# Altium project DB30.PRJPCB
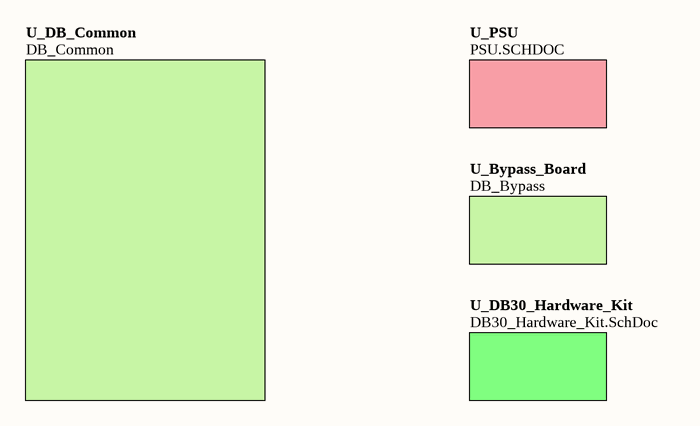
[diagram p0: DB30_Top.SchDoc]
ProjectAddress1: L3, 12A Rodborough Road; ProjectAddress2: Frenchs Forest; ProjectAddress3: NSW 2086; ProjectAddress4: Australia; ProjectAssyNum: D-820-0004; ProjectOrganization: Altium Limited; ProjectRevision: 07; ProjectTitle: DB30 - Daughter Board Spartan3; ProjectTotalSheets: 22
9 sheets, 135 parts. Net scope: hierarchical (ports join the sheet entries above them; power ports are global).
Board files: DB30_Panel.PcbDoc, DB30.PcbDoc
Sheets:
  DB30_Top.SchDoc
    U_PSU = PSU.SCHDOC
    U_DB30_Hardware_Kit = DB30_Hardware_Kit.SchDoc
  DEVICES.SchDoc
    U_FPGA = FPGA.SCHDOC
      U_FPGA_Power = FPGA_NonIO.SchDoc
      U_Bypass_3V3 = Bypass_FPGA_3V3.SchDoc
      U_Bypass_2V5 = Bypass_FPGA_2V5.SchDoc
      U_Bypass_1V2 = Bypass_FPGA_1V2.SchDoc

## Sheet DB30_Top.SchDoc: DB30 Top Level
size A4; Address1: Level 3, 12a Rodborough Rd; Address2: Frenchs Forest 2086; Address3: NSW; Address4: AUSTRALIA; SheetNumber: 2; SheetTotal: 23

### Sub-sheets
U_Bypass_Board = DB_Bypass (file not in this document): no entries
U_DB30_Hardware_Kit = DB30_Hardware_Kit.SchDoc: no entries
U_DB_Common = DB_Common (file not in this document): no entries
U_PSU = PSU.SCHDOC: no entries

## Sheet PSU.SCHDOC: Power Supply Top Level
size A4; Address1: Level 3, 12a Rodborough Rd; Address2: Frenchs Forest 2086; Address3: NSW; Address4: AUSTRALIA; SheetNumber: 10; SheetTotal: 23
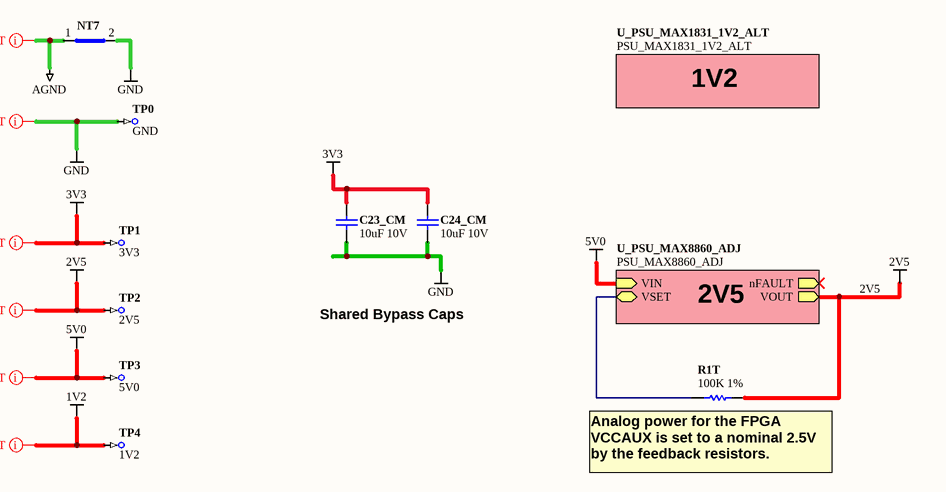
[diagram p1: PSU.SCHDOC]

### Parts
C23_CM  10uF 10V  [CAPC2012-STAR]
C24_CM  10uF 10V  [CAPC2012-STAR]
NT7  Net Tie SMT2  [NETTIE-SMT2-8X8]  (value not drawn)  (net tie, no BOM)
R1T  100K 1%  [RESC1005-STAR]
TP0  GND  [TestPin]  (no BOM)
TP1  3V3  [TestPin]  (no BOM)
TP2  2V5  [TestPin]  (no BOM)
TP3  5V0  [TestPin]  (no BOM)
TP4  1V2  [TestPin]  (no BOM)

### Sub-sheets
U_PSU_MAX1831_1V2_ALT = PSU_MAX1831_1V2_ALT (file not in this document): no entries
U_PSU_MAX8860_ADJ = PSU_MAX8860_ADJ (file not in this document): nFAULT (out), VIN (in), VOUT (out), VSET (bidir)

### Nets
1V2: TP4.1
2V5: R1T.2 TP2.1 ; sheet U_PSU_MAX8860_ADJ/VOUT
3V3: C23_CM.1 C24_CM.1 TP1.1
5V0: TP3.1 ; sheet U_PSU_MAX8860_ADJ/VIN
AGND: NT7.1(Net1)
GND: C23_CM.2 C24_CM.2 NT7.2(Net2) TP0.1
NetR1T_1: R1T.1 ; sheet U_PSU_MAX8860_ADJ/VSET

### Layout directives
net class PWRNET: 1V2, 2V5, 3V3, 5V0, AGND, GND

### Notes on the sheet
- 1V2
- Shared Bypass Caps
- 2V5
- (near R1T) Analog power for the FPGA VCCAUX is set to a nominal 2.5V by the feedback resistors.

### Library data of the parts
C23_CM C24_CM = D-101-0087: Capacitor, Ceramic, 10uF 10% 10V 0805 (2012) X5R; Polarity: Non-Polarized
NT7 = D-002-0002: Net-Tie, Surface Mount, 2 x 0.4mm x 0.2mm SMT Pads - For 0.2mm Track
R1T = D-100-0132: Resistor, 100K 1% 0402 (1005); Power Rating: 63 mW
TP0-TP4 = D-006-0000: Test Point, PCB Mount with Silkscreen Box

## Sheet DB30_Hardware_Kit.SchDoc: DB30 Hardware Kit
size A4; Address1: Level 3, 12a Rodborough Rd; Address2: Frenchs Forest 2086; Address3: NSW; Address4: AUSTRALIA; SheetNumber: 9; SheetTotal: 23
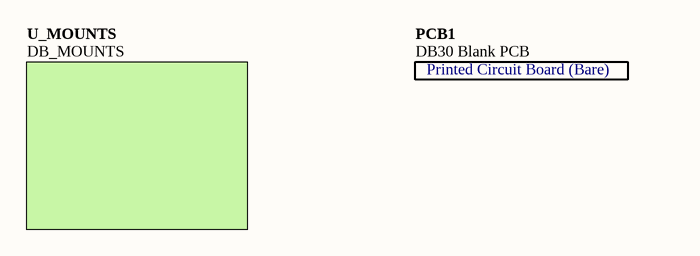
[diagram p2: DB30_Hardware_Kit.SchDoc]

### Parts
PCB1  DB30 Blank PCB  (mechanical)

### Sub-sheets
U_MOUNTS = DB_MOUNTS (file not in this document): no entries

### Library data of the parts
PCB1 = D-810-0004: DB30 Blank PCB - Daughter Board Xilinx Spartan3 XC3S1500-4FG676C; ProjectPath: DB30.PrjPCB

## Sheet DEVICES.SchDoc: FPGA, LEDs and SRAM Memory
size A4; Address1: Level 3, 12a Rodborough Rd; Address2: Frenchs Forest 2086; Address3: NSW; Address4: AUSTRALIA; SheetNumber: 3; SheetTotal: 23
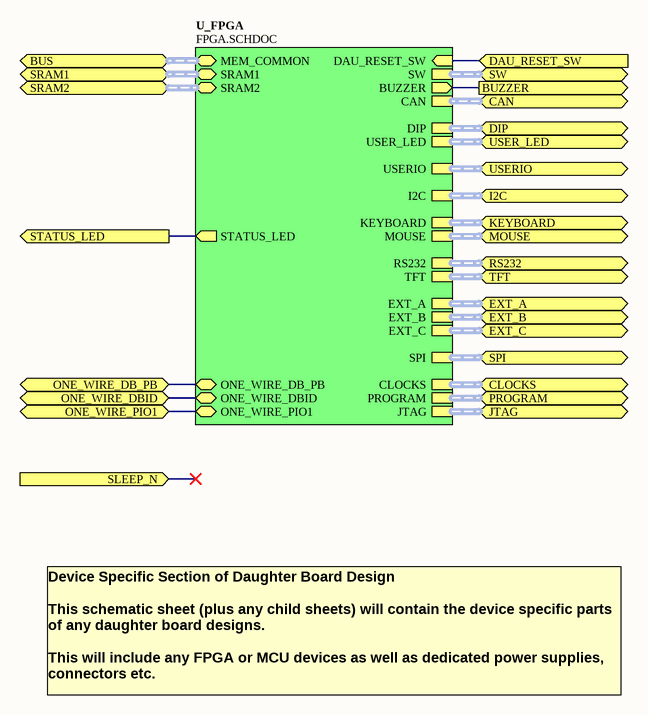
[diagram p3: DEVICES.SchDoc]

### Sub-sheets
U_FPGA = FPGA.SCHDOC: SRAM1 (harness SRAM-256Kx16), SRAM2 (harness SRAM-256Kx16), MEM_COMMON (harness HOSTMEMORY), DAU_RESET_SW (in), BUZZER (out), ONE_WIRE_DBID (bidir), ONE_WIRE_DB_PB (bidir), ONE_WIRE_PIO1 (bidir), JTAG (harness HardSoft_JTAG), SW (harness SW5), DIP (harness SW8), USERIO (harness IO36), EXT_A (harness PBIO), EXT_B (harness PBIO), EXT_C (harness PBIO), USER_LED (harness LED8), SPI (harness DAU_SPI), I2C (harness I2C), CAN (harness CAN_INT), RS232 (harness RS232_INT), KEYBOARD (harness PS2), MOUSE (harness PS2), TFT (harness DAU_TFT), PROGRAM (harness DAU_CTRL), CLOCKS (harness DAU_CLK), STATUS_LED (out)

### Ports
BUS (harness HOSTMEMORY), BUZZER (out), CAN, CLOCKS, DAU_RESET_SW (in), DIP, EXT_A, EXT_B, EXT_C, I2C, JTAG, KEYBOARD, MOUSE, ONE_WIRE_DB_PB (bidir), ONE_WIRE_DBID (bidir), ONE_WIRE_PIO1 (bidir), PROGRAM, RS232, SLEEP_N (in), SPI, SRAM1, SRAM2 (harness SRAM-256Kx16), STATUS_LED (out), SW, TFT, USER_LED, USERIO

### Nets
BUZZER: port BUZZER, sheet U_FPGA/BUZZER
DAU_RESET_SW: port DAU_RESET_SW, sheet U_FPGA/DAU_RESET_SW
ONE_WIRE_DB_PB: port ONE_WIRE_DB_PB, sheet U_FPGA/ONE_WIRE_DB_PB
ONE_WIRE_DBID: port ONE_WIRE_DBID, sheet U_FPGA/ONE_WIRE_DBID
ONE_WIRE_PIO1: port ONE_WIRE_PIO1, sheet U_FPGA/ONE_WIRE_PIO1
STATUS_LED: port STATUS_LED, sheet U_FPGA/STATUS_LED

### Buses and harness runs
harness port BUS = sheet U_FPGA/MEM_COMMON
harness port CAN = sheet U_FPGA/CAN
harness port CLOCKS = sheet U_FPGA/CLOCKS
harness port DIP = sheet U_FPGA/DIP
harness port EXT_A = sheet U_FPGA/EXT_A
harness port EXT_B = sheet U_FPGA/EXT_B
harness port EXT_C = sheet U_FPGA/EXT_C
harness port I2C = sheet U_FPGA/I2C
harness port JTAG = sheet U_FPGA/JTAG
harness port KEYBOARD = sheet U_FPGA/KEYBOARD
harness port MOUSE = sheet U_FPGA/MOUSE
harness port PROGRAM = sheet U_FPGA/PROGRAM
harness port RS232 = sheet U_FPGA/RS232
harness port SPI = sheet U_FPGA/SPI
harness port SRAM1 = sheet U_FPGA/SRAM1
harness port SRAM2 = sheet U_FPGA/SRAM2
harness port SW = sheet U_FPGA/SW
harness port TFT = sheet U_FPGA/TFT
harness port USER_LED = sheet U_FPGA/USER_LED
harness port USERIO = sheet U_FPGA/USERIO

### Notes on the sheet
- Device Specific Section of Daughter Board Design
  This schematic sheet (plus any child sheets) will contain the device specific parts of any daughter board designs.
  This will include any FPGA or MCU devices as well as dedicated power supplies, connectors etc.

## Sheet FPGA.SCHDOC: FPGA Connections
size A2; Address1: Level 3, 12a Rodborough Rd; Address2: Frenchs Forest 2086; Address3: NSW; Address4: AUSTRALIA; SheetNumber: 4; SheetTotal: 23; PageSetup: Record=PageOptions|CenterHorizontal=True|CenterVertical=True|PrintScale=0.71|XCorrection=1.00|YCorrection=1.00|PrintKind=0|BorderSize=5000000|LeftOffset=0|BottomOffset=0|Orientation=2|PaperLength=4199|PaperWidth=2969|Scale=100|PaperSource=7|PrintQuality=600|MediaType=1|DitherType=10|PaperKind=A3 (297 x 420 mm)|PrintScaleMode=1
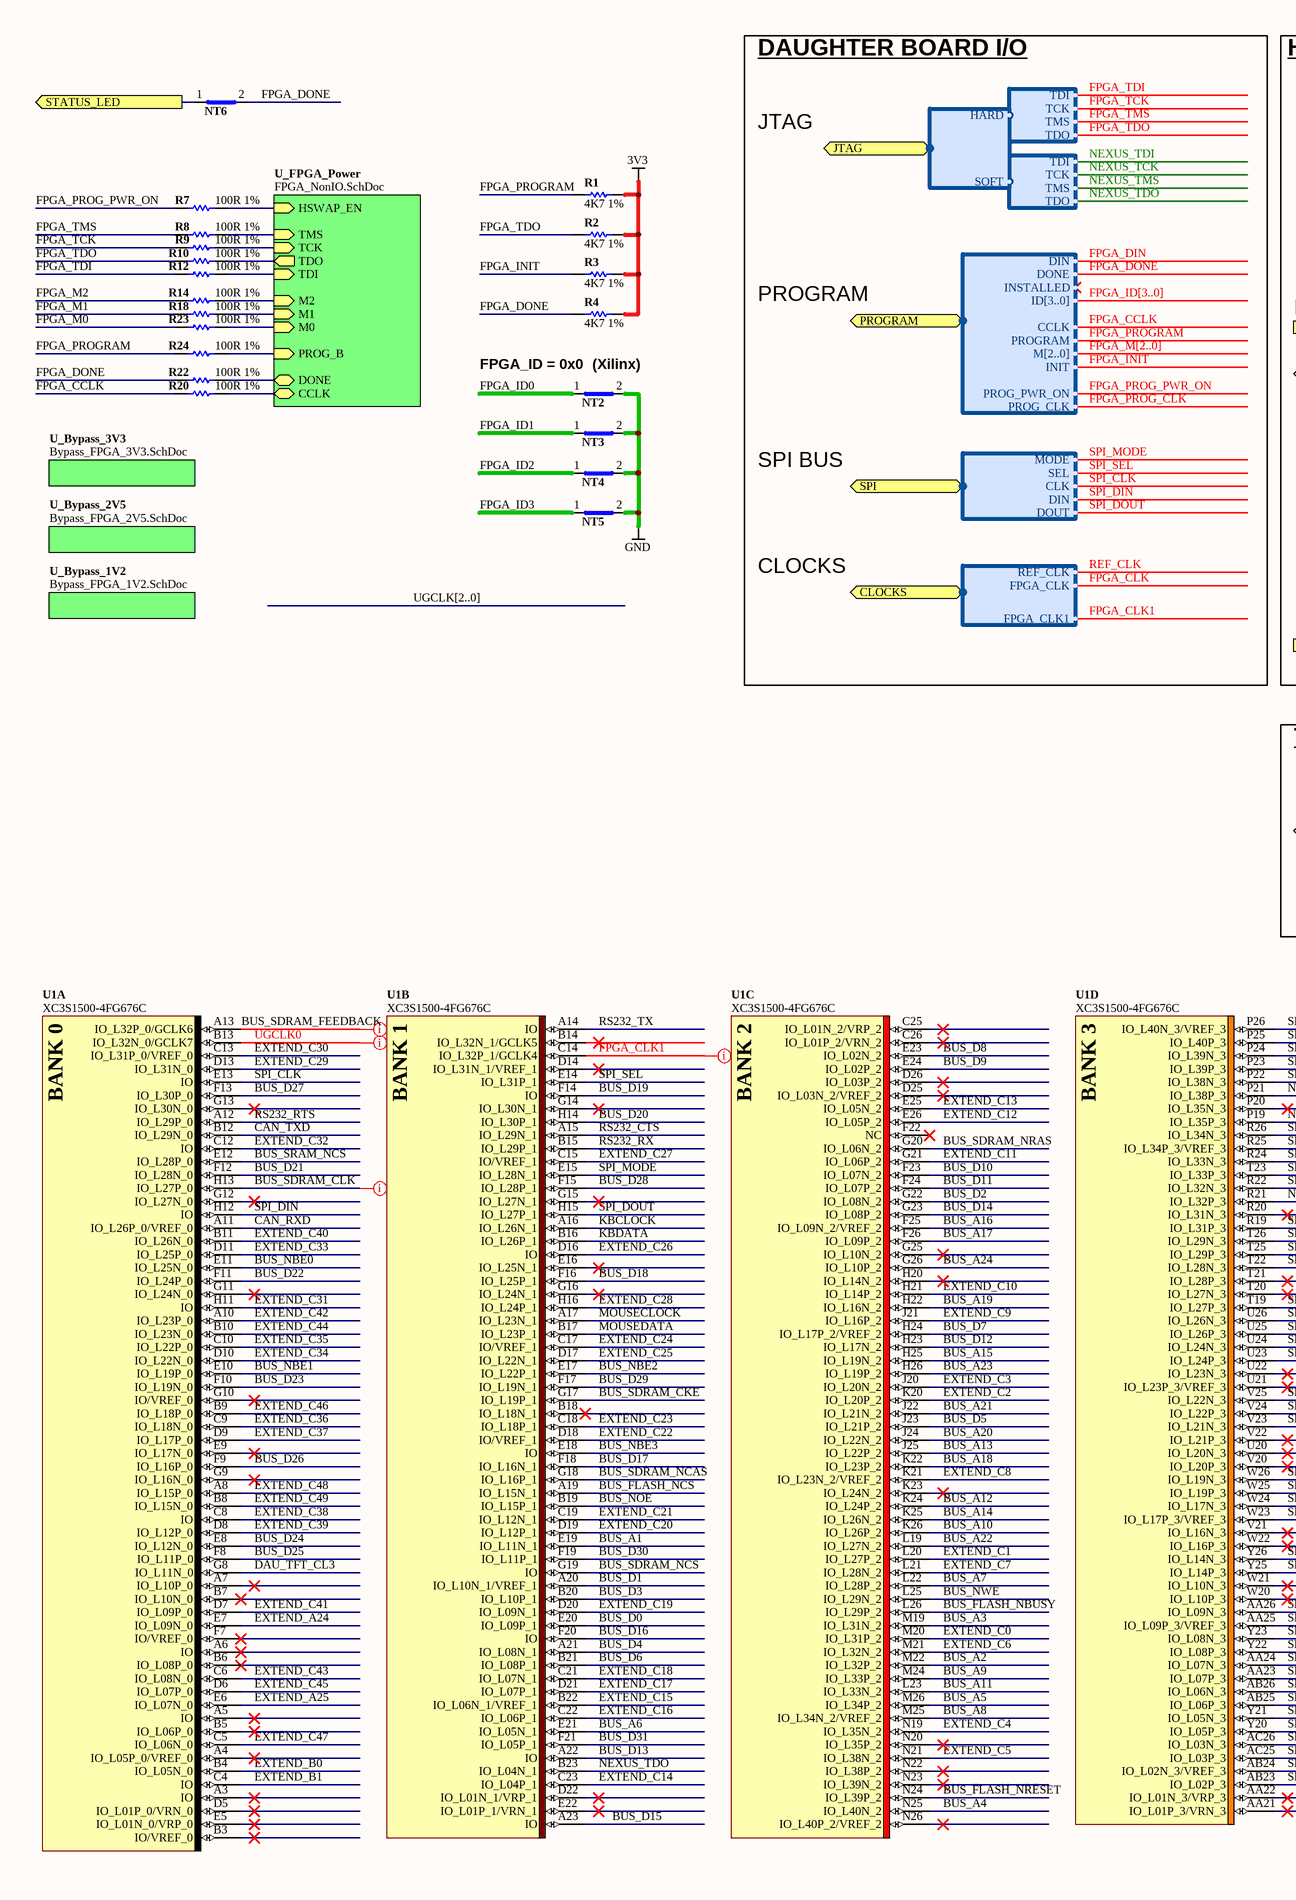
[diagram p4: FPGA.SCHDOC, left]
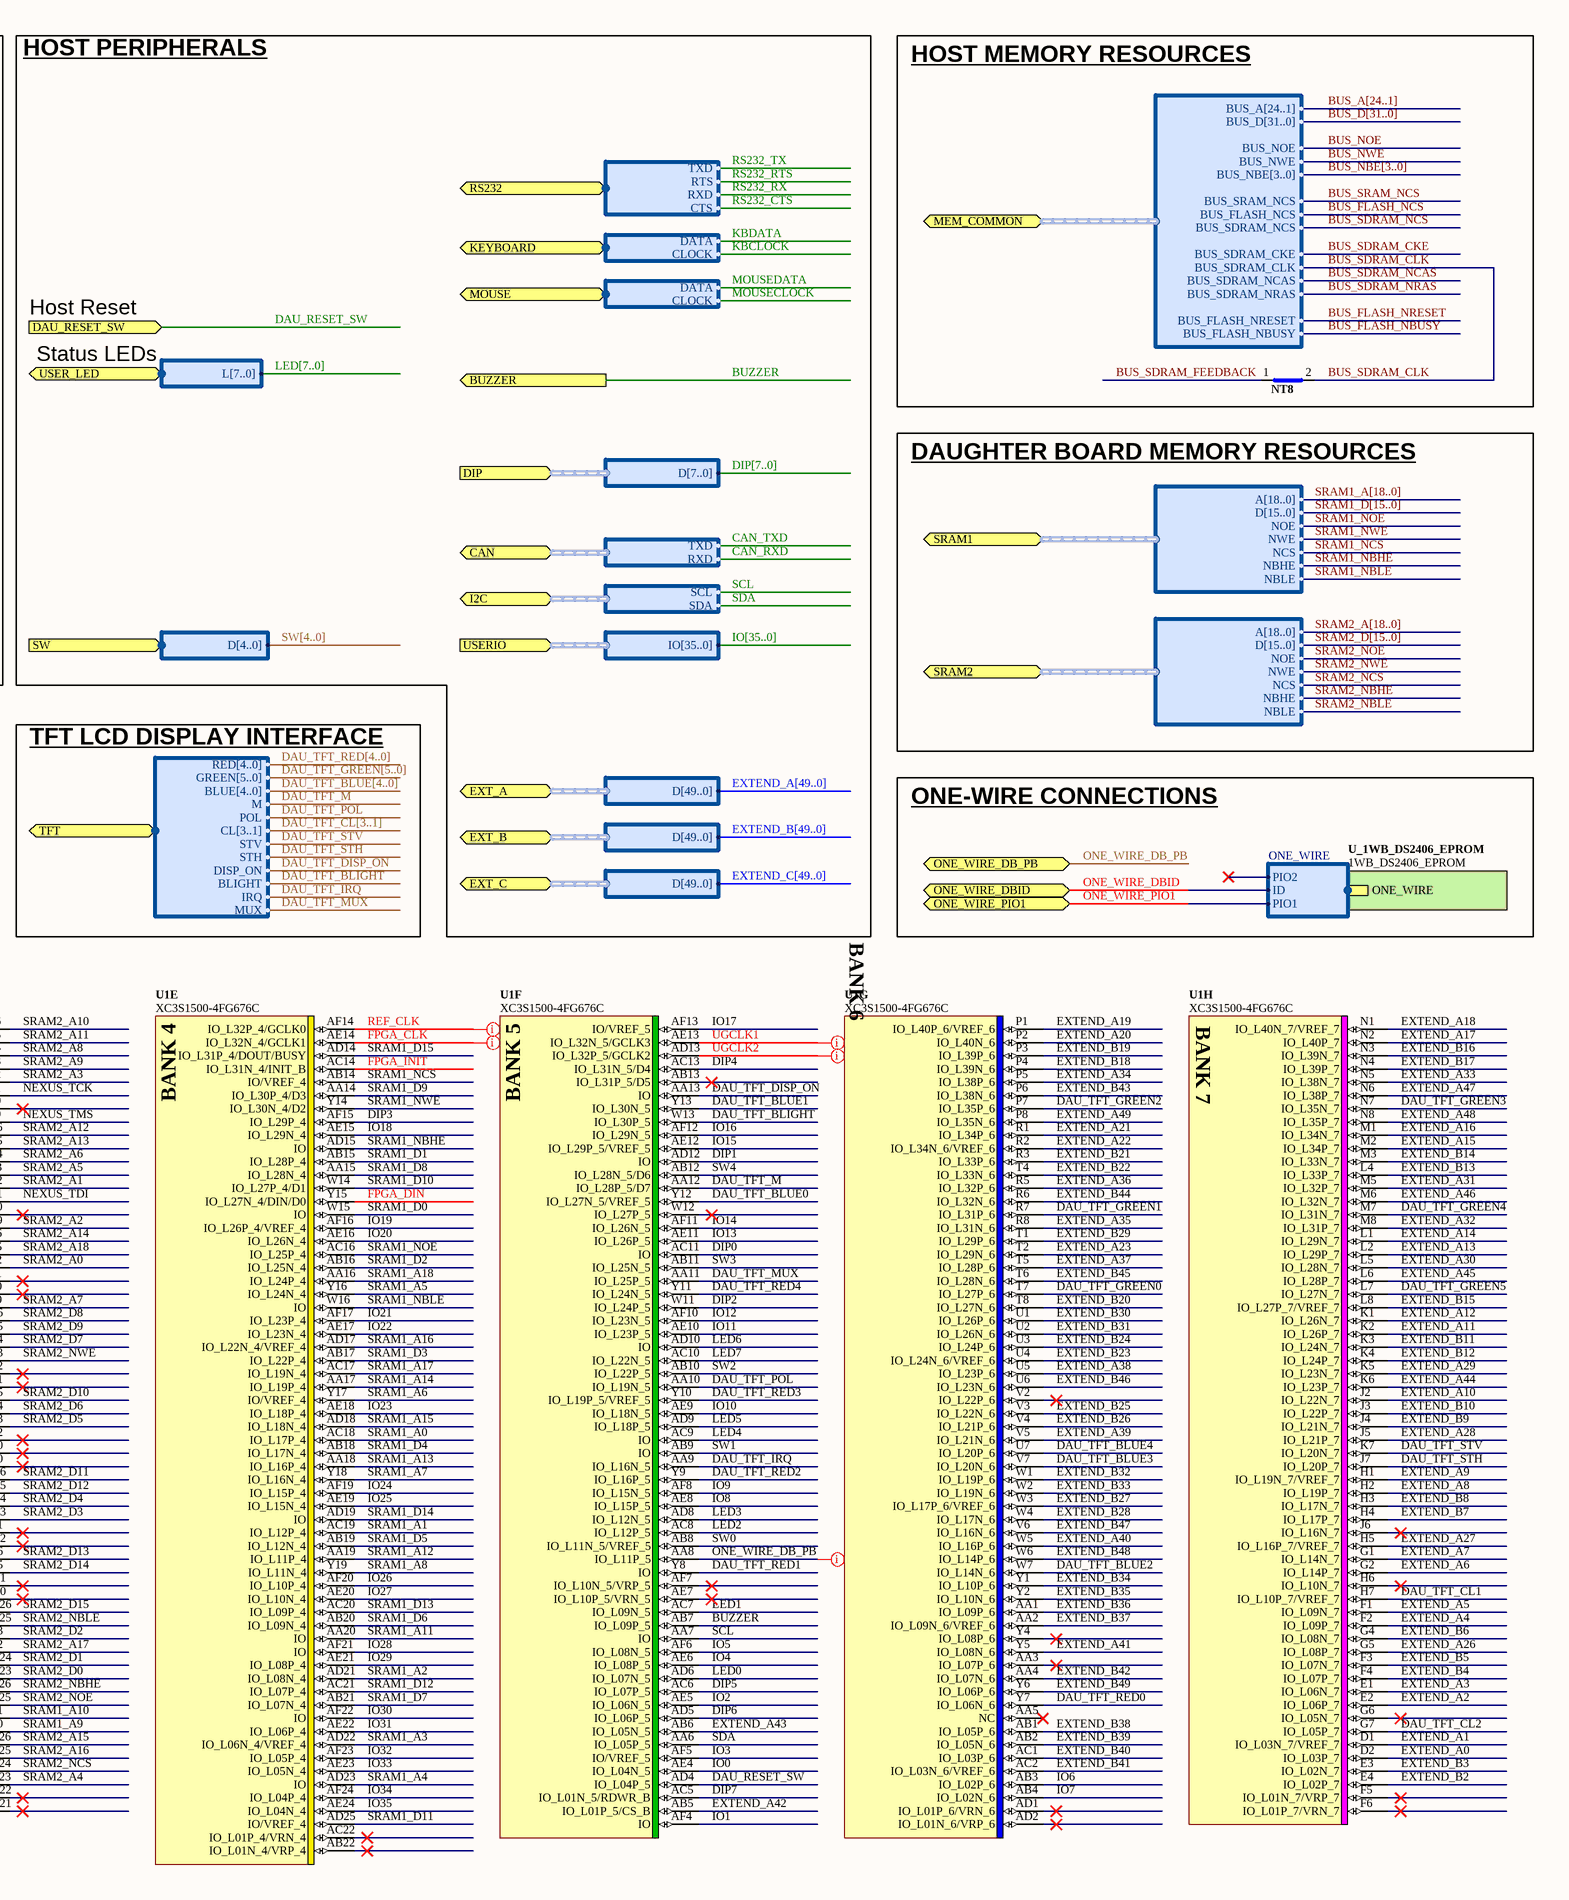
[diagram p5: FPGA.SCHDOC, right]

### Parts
NT2  Net Tie SMT2  [NETTIE-SMT2-8X8]  (value not drawn)  (net tie, no BOM)
NT3  Net Tie SMT2  [NETTIE-SMT2-8X8]  (value not drawn)  (net tie, no BOM)
NT4  Net Tie SMT2  [NETTIE-SMT2-8X8]  (value not drawn)  (net tie, no BOM)
NT5  Net Tie SMT2  [NETTIE-SMT2-8X8]  (value not drawn)  (net tie, no BOM)
NT6  Net Tie SMT2  [NETTIE-SMT2-8X8]  (value not drawn)  (net tie, no BOM)
NT8  Net Tie SMT2  [NETTIE-SMT2-8X8]  (value not drawn)  (net tie, no BOM)
R1  4K7 1%  [RESC1005-STAR]
R2  4K7 1%  [RESC1005-STAR]
R3  4K7 1%  [RESC1005-STAR]
R4  4K7 1%  [RESC1005-STAR]
R7  100R 1%  [RESC1005-STAR]
R8  100R 1%  [RESC1005-STAR]
R9  100R 1%  [RESC1005-STAR]
R10  100R 1%  [RESC1005-STAR]
R12  100R 1%  [RESC1005-STAR]
R14  100R 1%  [RESC1005-STAR]
R18  100R 1%  [RESC1005-STAR]
R20  100R 1%  [RESC1005-STAR]
R22  100R 1%  [RESC1005-STAR]
R23  100R 1%  [RESC1005-STAR]
R24  100R 1%  [RESC1005-STAR]
U1  XC3S1500-4FG676C  [BGA100P26X26-676]  (parts A,B,C,D,E,F,G,H of 12)

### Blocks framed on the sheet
HOST MEMORY RESOURCES: NT8

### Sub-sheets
U_1WB_DS2406_EPROM = 1WB_DS2406_EPROM (file not in this document): ONE_WIRE (harness ONE_WIRE)
U_Bypass_1V2 = Bypass_FPGA_1V2.SchDoc: no entries
U_Bypass_2V5 = Bypass_FPGA_2V5.SchDoc: no entries
U_Bypass_3V3 = Bypass_FPGA_3V3.SchDoc: no entries
U_FPGA_Power = FPGA_NonIO.SchDoc: TMS (in), DONE (bidir), M1 (in), CCLK (bidir), M0 (in), M2 (in), TCK (in), HSWAP_EN (in), TDI (in), PROG_B (in), TDO (out)

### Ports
BUZZER (out), CAN (harness CAN_INT), CLOCKS (harness DAU_CLK), DAU_RESET_SW (in), DIP (harness SW8), EXT_A (harness PBIO), EXT_B (harness PBIO), EXT_C (harness PBIO), I2C (harness I2C), JTAG (harness HARDSOFT_JTAG), KEYBOARD (harness PS2), MEM_COMMON (harness HOSTMEMORY), MOUSE (harness PS2), ONE_WIRE_DB_PB (bidir), ONE_WIRE_DBID (bidir), ONE_WIRE_PIO1 (bidir), PROGRAM (harness DAU_CTRL), RS232 (harness RS232_INT), SPI (harness DAU_SPI), SRAM1 (harness SRAM-256Kx16), SRAM2 (harness SRAM-256Kx16), STATUS_LED (out), SW (harness SW5), TFT (harness DAU_TFT), USER_LED (harness LED8), USERIO (harness IO36)

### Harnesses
ONE_WIRE: ID, PIO1, PIO2
SRAM-256Kx16: A[18..0], D[15..0], NCS, NWE, NOE, NBHE, NBLE
HOSTMEMORY: BUS_A[24..1], BUS_D[31..0], BUS_NOE, BUS_NWE, BUS_NBE[3..0], BUS_SRAM_NCS, BUS_FLASH_NCS, BUS_SDRAM_NCS, BUS_SDRAM_CKE, BUS_SDRAM_CLK, BUS_SDRAM_NCAS, BUS_SDRAM_NRAS, BUS_FLASH_NRESET, BUS_FLASH_NBUSY
DAU_CLK: REF_CLK, FPGA_CLK, FPGA_CLK1
DAU_SPI: MODE, SEL, CLK, DIN, DOUT
DAU_CTRL: DIN, DONE, INSTALLED, ID[3..0], CCLK, PROGRAM, M[2..0], INIT, PROG_PWR_ON, PROG_CLK
JTAG: TMS, TDO, TDI, TCK
HARDSOFT_JTAG: HARD, SOFT
LED8: L[7..0]
SW5: D[4..0]
DAU_TFT: RED[4..0], GREEN[5..0], BLUE[4..0], M, POL, CL[3..1], STV, STH, DISP_ON, BLIGHT, IRQ, MUX
PS2: DATA, CLOCK
RS232_INT: RXD, TXD, RTS, CTS
IO36: IO[35..0]
SW8: D[7..0]
CAN_INT: TXD, RXD
I2C: SCL, SDA
PBIO: D[49..0]

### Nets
3V3: R1.2 R2.2 R3.2 R4.2
GND: NT2.2(Net2) NT3.2(Net2) NT4.2(Net2) NT5.2(Net2)
BUS_A1: U1.E19(IO_L11N_1)
BUS_A2: U1.M22(IO_L32P_2)
BUS_A3: U1.M19(IO_L31N_2)
BUS_A4: U1.N25(IO_L40N_2)
BUS_A5: U1.M26(IO_L34P_2)
BUS_A6: U1.E21(IO_L05N_1)
BUS_A7: U1.L22(IO_L28P_2)
BUS_A8: U1.M25(IO_L34N_2/VREF_2)
BUS_A9: U1.M24(IO_L33P_2)
BUS_A10: U1.K26(IO_L26P_2)
BUS_A11: U1.L23(IO_L33N_2)
BUS_A12: U1.K24(IO_L24P_2)
BUS_A13: U1.J25(IO_L22P_2)
BUS_A14: U1.K25(IO_L26N_2)
BUS_A15: U1.H25(IO_L19N_2)
BUS_A16: U1.F25(IO_L09N_2/VREF_2)
BUS_A17: U1.F26(IO_L09P_2)
BUS_A18: U1.K22(IO_L23P_2)
BUS_A19: U1.H22(IO_L16N_2)
BUS_A20: U1.J24(IO_L22N_2)
BUS_A21: U1.J22(IO_L21N_2)
BUS_A22: U1.L19(IO_L27N_2)
BUS_A23: U1.H26(IO_L19P_2)
BUS_A24: U1.G26(IO_L10P_2)
BUS_D0: U1.E20(IO_L09P_1)
BUS_D1: U1.A20(IO_L10N_1/VREF_1)
BUS_D2: U1.G22(IO_L08N_2)
BUS_D3: U1.B20(IO_L10P_1)
BUS_D4: U1.A21(IO_L08N_1)
BUS_D5: U1.J23(IO_L21P_2)
BUS_D6: U1.B21(IO_L08P_1)
BUS_D7: U1.H24(IO_L17P_2/VREF_2)
BUS_D8: U1.E23(IO_L02N_2)
BUS_D9: U1.E24(IO_L02P_2)
BUS_D10: U1.F23(IO_L07N_2)
BUS_D11: U1.F24(IO_L07P_2)
BUS_D12: U1.H23(IO_L17N_2)
BUS_D13: U1.A22(IO)
BUS_D14: U1.G23(IO_L08P_2)
BUS_D15: U1.A23(IO)
BUS_D16: U1.F20(IO)
BUS_D17: U1.F18(IO_L16N_1)
BUS_D18: U1.F16(IO_L25P_1)
BUS_D19: U1.F14(IO)
BUS_D20: U1.H14(IO_L30P_1)
BUS_D21: U1.F12(IO_L28N_0)
BUS_D22: U1.F11(IO_L24P_0)
BUS_D23: U1.F10(IO_L19N_0)
BUS_D24: U1.E8(IO_L12N_0)
BUS_D25: U1.F8(IO_L11P_0)
BUS_D26: U1.F9(IO_L16P_0)
BUS_D27: U1.F13(IO_L30P_0)
BUS_D28: U1.F15(IO_L28P_1)
BUS_D29: U1.F17(IO_L19N_1)
BUS_D30: U1.F19(IO_L11P_1)
BUS_D31: U1.F21(IO_L05P_1)
BUS_FLASH_NBUSY: U1.L26(IO_L29P_2) ; port MEM_COMMON.BUS_FLASH_NBUSY
BUS_FLASH_NCS: U1.A19(IO_L15N_1) ; port MEM_COMMON.BUS_FLASH_NCS
BUS_FLASH_NRESET: U1.N24(IO_L39P_2) ; port MEM_COMMON.BUS_FLASH_NRESET
BUS_NBE0: U1.E11(IO_L25N_0)
BUS_NBE1: U1.E10(IO_L19P_0)
BUS_NBE2: U1.E17(IO_L22P_1)
BUS_NBE3: U1.E18(IO)
BUS_NOE: U1.B19(IO_L15P_1) ; port MEM_COMMON.BUS_NOE
BUS_NWE: U1.L25(IO_L29N_2) ; port MEM_COMMON.BUS_NWE
BUS_SDRAM_CKE: U1.G17(IO_L19P_1) ; port MEM_COMMON.BUS_SDRAM_CKE
BUS_SDRAM_CLK: NT8.2(Net2) U1.H13(IO_L27P_0) ; port MEM_COMMON.BUS_SDRAM_CLK
BUS_SDRAM_FEEDBACK: NT8.1(Net1) U1.A13(IO_L32P_0/GCLK6)
BUS_SDRAM_NCAS: U1.G18(IO_L16P_1) ; port MEM_COMMON.BUS_SDRAM_NCAS
BUS_SDRAM_NCS: U1.G19(IO) ; port MEM_COMMON.BUS_SDRAM_NCS
BUS_SDRAM_NRAS: U1.G20(IO_L06N_2) ; port MEM_COMMON.BUS_SDRAM_NRAS
BUS_SRAM_NCS: U1.E12(IO_L28P_0) ; port MEM_COMMON.BUS_SRAM_NCS
BUZZER: U1.AB7(IO_L09P_5) ; port BUZZER
CAN_RXD: U1.A11(IO_L26P_0/VREF_0) ; port CAN.RXD
CAN_TXD: U1.B12(IO_L29N_0) ; port CAN.TXD
CCLK: R20.2 ; sheet U_FPGA_Power/CCLK
DAU_RESET_SW: U1.AD4(IO_L04P_5) ; port DAU_RESET_SW
DAU_TFT_BLIGHT: U1.W13(IO_L30P_5) ; port TFT.BLIGHT
DAU_TFT_BLUE0: U1.Y12(IO_L27N_5/VREF_5)
DAU_TFT_BLUE1: U1.Y13(IO_L30N_5)
DAU_TFT_BLUE2: U1.W7(IO_L14N_6)
DAU_TFT_BLUE3: U1.V7(IO_L20N_6)
DAU_TFT_BLUE4: U1.U7(IO_L20P_6)
DAU_TFT_CL1: U1.H7(IO_L10P_7/VREF_7)
DAU_TFT_CL2: U1.G7(IO_L05P_7)
DAU_TFT_CL3: U1.G8(IO_L11N_0)
DAU_TFT_DISP_ON: U1.AA13(IO) ; port TFT.DISP_ON
DAU_TFT_GREEN0: U1.T7(IO_L27P_6)
DAU_TFT_GREEN1: U1.R7(IO_L31P_6)
DAU_TFT_GREEN2: U1.P7(IO_L35P_6)
DAU_TFT_GREEN3: U1.N7(IO_L35N_7)
DAU_TFT_GREEN4: U1.M7(IO_L31N_7)
DAU_TFT_GREEN5: U1.L7(IO_L27N_7)
DAU_TFT_IRQ: U1.AA9(IO_L16N_5) ; port TFT.IRQ
DAU_TFT_M: U1.AA12(IO_L28P_5/D7) ; port TFT.M
DAU_TFT_MUX: U1.AA11(IO_L25P_5) ; port TFT.MUX
DAU_TFT_POL: U1.AA10(IO_L19N_5) ; port TFT.POL
DAU_TFT_RED0: U1.Y7(IO_L06N_6)
DAU_TFT_RED1: U1.Y8(IO)
DAU_TFT_RED2: U1.Y9(IO_L16P_5)
DAU_TFT_RED3: U1.Y10(IO_L19P_5/VREF_5)
DAU_TFT_RED4: U1.Y11(IO_L24N_5)
DAU_TFT_STH: U1.J7(IO_L20P_7) ; port TFT.STH
DAU_TFT_STV: U1.K7(IO_L20N_7) ; port TFT.STV
DIP0: U1.AC11(IO)
DIP1: U1.AD12(IO)
DIP2: U1.W11(IO_L24P_5)
DIP3: U1.AF15(IO_L29P_4)
DIP4: U1.AC13(IO_L31N_5/D4)
DIP5: U1.AC6(IO_L07P_5)
DIP6: U1.AD5(IO_L06P_5)
DIP7: U1.AC5(IO_L01N_5/RDWR_B)
DONE: R22.2 ; sheet U_FPGA_Power/DONE
EXTEND_A0: U1.D2(IO_L03P_7)
EXTEND_A1: U1.D1(IO_L03N_7/VREF_7)
EXTEND_A2: U1.E2(IO_L06P_7)
EXTEND_A3: U1.E1(IO_L06N_7)
EXTEND_A4: U1.F2(IO_L09P_7)
EXTEND_A5: U1.F1(IO_L09N_7)
EXTEND_A6: U1.G2(IO_L14P_7)
EXTEND_A7: U1.G1(IO_L14N_7)
EXTEND_A8: U1.H2(IO_L19P_7)
EXTEND_A9: U1.H1(IO_L19N_7/VREF_7)
EXTEND_A10: U1.J2(IO_L22N_7)
EXTEND_A11: U1.K2(IO_L26P_7)
EXTEND_A12: U1.K1(IO_L26N_7)
EXTEND_A13: U1.L2(IO_L29P_7)
EXTEND_A14: U1.L1(IO_L29N_7)
EXTEND_A15: U1.M2(IO_L34P_7)
EXTEND_A16: U1.M1(IO_L34N_7)
EXTEND_A17: U1.N2(IO_L40P_7)
EXTEND_A18: U1.N1(IO_L40N_7/VREF_7)
EXTEND_A19: U1.P1(IO_L40P_6/VREF_6)
EXTEND_A20: U1.P2(IO_L40N_6)
EXTEND_A21: U1.R1(IO_L34P_6)
EXTEND_A22: U1.R2(IO_L34N_6/VREF_6)
EXTEND_A23: U1.T2(IO_L29N_6)
EXTEND_A24: U1.E7(IO_L09N_0)
EXTEND_A25: U1.E6(IO_L07N_0)
EXTEND_A26: U1.G5(IO_L08P_7)
EXTEND_A27: U1.H5(IO_L16P_7/VREF_7)
EXTEND_A28: U1.J5(IO_L21P_7)
EXTEND_A29: U1.K5(IO_L23N_7)
EXTEND_A30: U1.L5(IO_L28N_7)
EXTEND_A31: U1.M5(IO_L32P_7)
EXTEND_A32: U1.M8(IO_L31P_7)
EXTEND_A33: U1.N5(IO_L38N_7)
EXTEND_A34: U1.P5(IO_L38P_6)
EXTEND_A35: U1.R8(IO_L31N_6)
EXTEND_A36: U1.R5(IO_L32P_6)
EXTEND_A37: U1.T5(IO_L28P_6)
EXTEND_A38: U1.U5(IO_L23P_6)
EXTEND_A39: U1.V5(IO_L21N_6)
EXTEND_A40: U1.W5(IO_L16P_6)
EXTEND_A41: U1.Y5(IO_L08N_6)
EXTEND_A42: U1.AB5(IO_L01P_5/CS_B)
EXTEND_A43: U1.AB6(IO_L05N_5)
EXTEND_A44: U1.K6(IO_L23P_7)
EXTEND_A45: U1.L6(IO_L28P_7)
EXTEND_A46: U1.M6(IO_L32N_7)
EXTEND_A47: U1.N6(IO_L38P_7)
EXTEND_A48: U1.N8(IO_L35P_7)
EXTEND_A49: U1.P8(IO_L35N_6)
EXTEND_B0: U1.B4(IO_L05N_0)
EXTEND_B1: U1.C4(IO)
EXTEND_B2: U1.E4(IO_L02P_7)
EXTEND_B3: U1.E3(IO_L02N_7)
EXTEND_B4: U1.F4(IO_L07P_7)
EXTEND_B5: U1.F3(IO_L07N_7)
EXTEND_B6: U1.G4(IO_L08N_7)
EXTEND_B7: U1.H4(IO_L17P_7)
EXTEND_B8: U1.H3(IO_L17N_7)
EXTEND_B9: U1.J4(IO_L21N_7)
EXTEND_B10: U1.J3(IO_L22P_7)
EXTEND_B11: U1.K3(IO_L24N_7)
EXTEND_B12: U1.K4(IO_L24P_7)
EXTEND_B13: U1.L4(IO_L33P_7)
EXTEND_B14: U1.M3(IO_L33N_7)
EXTEND_B15: U1.L8(IO_L27P_7/VREF_7)
EXTEND_B16: U1.N3(IO_L39N_7)
EXTEND_B17: U1.N4(IO_L39P_7)
EXTEND_B18: U1.P4(IO_L39N_6)
EXTEND_B19: U1.P3(IO_L39P_6)
EXTEND_B20: U1.T8(IO_L27N_6)
EXTEND_B21: U1.R3(IO_L33P_6)
EXTEND_B22: U1.T4(IO_L33N_6)
EXTEND_B23: U1.U4(IO_L24N_6/VREF_6)
EXTEND_B24: U1.U3(IO_L24P_6)
EXTEND_B25: U1.V3(IO_L22N_6)
EXTEND_B26: U1.V4(IO_L21P_6)
EXTEND_B27: U1.W3(IO_L17P_6/VREF_6)
EXTEND_B28: U1.W4(IO_L17N_6)
EXTEND_B29: U1.T1(IO_L29P_6)
EXTEND_B30: U1.U1(IO_L26P_6)
EXTEND_B31: U1.U2(IO_L26N_6)
EXTEND_B32: U1.W1(IO_L19P_6)
EXTEND_B33: U1.W2(IO_L19N_6)
EXTEND_B34: U1.Y1(IO_L10P_6)
EXTEND_B35: U1.Y2(IO_L10N_6)
EXTEND_B36: U1.AA1(IO_L09P_6)
EXTEND_B37: U1.AA2(IO_L09N_6/VREF_6)
EXTEND_B38: U1.AB1(IO_L05P_6)
EXTEND_B39: U1.AB2(IO_L05N_6)
EXTEND_B40: U1.AC1(IO_L03P_6)
EXTEND_B41: U1.AC2(IO_L03N_6/VREF_6)
EXTEND_B42: U1.AA4(IO_L07N_6)
EXTEND_B43: U1.P6(IO_L38N_6)
EXTEND_B44: U1.R6(IO_L32N_6)
EXTEND_B45: U1.T6(IO_L28N_6)
EXTEND_B46: U1.U6(IO_L23N_6)
EXTEND_B47: U1.V6(IO_L16N_6)
EXTEND_B48: U1.W6(IO_L14P_6)
EXTEND_B49: U1.Y6(IO_L06P_6)
EXTEND_C0: U1.M20(IO_L31P_2)
EXTEND_C1: U1.L20(IO_L27P_2)
EXTEND_C2: U1.K20(IO_L20P_2)
EXTEND_C3: U1.J20(IO_L20N_2)
EXTEND_C4: U1.N19(IO_L35N_2)
EXTEND_C5: U1.N21(IO_L38N_2)
EXTEND_C6: U1.M21(IO_L32N_2)
EXTEND_C7: U1.L21(IO_L28N_2)
EXTEND_C8: U1.K21(IO_L23N_2/VREF_2)
EXTEND_C9: U1.J21(IO_L16P_2)
EXTEND_C10: U1.H21(IO_L14P_2)
EXTEND_C11: U1.G21(IO_L06P_2)
EXTEND_C12: U1.E26(IO_L05P_2)
EXTEND_C13: U1.E25(IO_L05N_2)
EXTEND_C14: U1.C23(IO_L04P_1)
EXTEND_C15: U1.B22(IO_L06N_1/VREF_1)
EXTEND_C16: U1.C22(IO_L06P_1)
EXTEND_C17: U1.D21(IO_L07P_1)
EXTEND_C18: U1.C21(IO_L07N_1)
EXTEND_C19: U1.D20(IO_L09N_1)
EXTEND_C20: U1.D19(IO_L12P_1)
EXTEND_C21: U1.C19(IO_L12N_1)
EXTEND_C22: U1.D18(IO/VREF_1)
EXTEND_C23: U1.C18(IO_L18P_1)
EXTEND_C24: U1.C17(IO/VREF_1)
EXTEND_C25: U1.D17(IO_L22N_1)
EXTEND_C26: U1.D16(IO)
EXTEND_C27: U1.C15(IO/VREF_1)
EXTEND_C28: U1.H16(IO_L24P_1)
EXTEND_C29: U1.D13(IO_L31N_0)
EXTEND_C30: U1.C13(IO_L31P_0/VREF_0)
EXTEND_C31: U1.H11(IO)
EXTEND_C32: U1.C12(IO)
EXTEND_C33: U1.D11(IO_L25P_0)
EXTEND_C34: U1.D10(IO_L22N_0)
EXTEND_C35: U1.C10(IO_L22P_0)
EXTEND_C36: U1.C9(IO_L18N_0)
EXTEND_C37: U1.D9(IO_L17P_0)
EXTEND_C38: U1.C8(IO)
EXTEND_C39: U1.D8(IO_L12P_0)
EXTEND_C40: U1.B11(IO_L26N_0)
EXTEND_C41: U1.D7(IO_L09P_0)
EXTEND_C42: U1.A10(IO_L23P_0)
EXTEND_C43: U1.C6(IO_L08N_0)
EXTEND_C44: U1.B10(IO_L23N_0)
EXTEND_C45: U1.D6(IO_L07P_0)
EXTEND_C46: U1.B9(IO_L18P_0)
EXTEND_C47: U1.C5(IO_L06N_0)
EXTEND_C48: U1.A8(IO_L15P_0)
EXTEND_C49: U1.B8(IO_L15N_0)
FPGA_CCLK: R20.1 ; port PROGRAM.CCLK
FPGA_CLK: U1.AE14(IO_L32N_4/GCLK1) ; port CLOCKS.FPGA_CLK
FPGA_CLK1: U1.C14(IO_L32P_1/GCLK4) ; port CLOCKS.FPGA_CLK1
FPGA_DIN: U1.Y15(IO_L27N_4/DIN/D0) ; port PROGRAM.DIN
FPGA_DONE: NT6.2(Net2) R4.1 R22.1 ; port PROGRAM.DONE
FPGA_ID0: NT2.1(Net1)
FPGA_ID1: NT3.1(Net1)
FPGA_ID2: NT4.1(Net1)
FPGA_ID3: NT5.1(Net1)
FPGA_INIT: R3.1 U1.AC14(IO_L31N_4/INIT_B) ; port PROGRAM.INIT
FPGA_M0: R23.1
FPGA_M1: R18.1
FPGA_M2: R14.1
FPGA_PROG_PWR_ON: R7.1 ; port PROGRAM.PROG_PWR_ON
FPGA_PROGRAM: R1.1 R24.1 ; port PROGRAM.PROGRAM
FPGA_TCK: R9.1 ; harness JTAG.TCK
FPGA_TDI: R12.1 ; harness JTAG.TDI
FPGA_TDO: R2.1 R10.1 ; harness JTAG.TDO
FPGA_TMS: R8.1 ; harness JTAG.TMS
HSWAP_EN: R7.2 ; sheet U_FPGA_Power/HSWAP_EN
IO0: U1.AE4(IO_L04N_5)
IO1: U1.AF4(IO)
IO2: U1.AE5(IO_L06N_5)
IO3: U1.AF5(IO/VREF_5)
IO4: U1.AE6(IO_L08P_5)
IO5: U1.AF6(IO_L08N_5)
IO6: U1.AB3(IO_L02P_6)
IO7: U1.AB4(IO_L02N_6)
IO8: U1.AE8(IO_L15P_5)
IO9: U1.AF8(IO_L15N_5)
IO10: U1.AE9(IO_L18N_5)
IO11: U1.AE10(IO_L23P_5)
IO12: U1.AF10(IO_L23N_5)
IO13: U1.AE11(IO_L26P_5)
IO14: U1.AF11(IO_L26N_5)
IO15: U1.AE12(IO_L29P_5/VREF_5)
IO16: U1.AF12(IO_L29N_5)
IO17: U1.AF13(IO/VREF_5)
IO18: U1.AE15(IO_L29N_4)
IO19: U1.AF16(IO_L26P_4/VREF_4)
IO20: U1.AE16(IO_L26N_4)
IO21: U1.AF17(IO_L23P_4)
IO22: U1.AE17(IO_L23N_4)
IO23: U1.AE18(IO_L18P_4)
IO24: U1.AF19(IO_L15P_4)
IO25: U1.AE19(IO_L15N_4)
IO26: U1.AF20(IO_L10P_4)
IO27: U1.AE20(IO_L10N_4)
IO28: U1.AF21(IO)
IO29: U1.AE21(IO_L08P_4)
IO30: U1.AF22(IO)
IO31: U1.AE22(IO_L06P_4)
IO32: U1.AF23(IO_L05P_4)
IO33: U1.AE23(IO_L05N_4)
IO34: U1.AF24(IO_L04P_4)
IO35: U1.AE24(IO_L04N_4)
KBCLOCK: U1.A16(IO_L26N_1) ; port KEYBOARD.CLOCK
KBDATA: U1.B16(IO_L26P_1) ; port KEYBOARD.DATA
LED0: U1.AD6(IO_L07N_5)
LED1: U1.AC7(IO_L09N_5)
LED2: U1.AC8(IO_L12P_5)
LED3: U1.AD8(IO_L12N_5)
LED4: U1.AC9(IO)
LED5: U1.AD9(IO_L18P_5)
LED6: U1.AD10(IO)
LED7: U1.AC10(IO_L22N_5)
M0: R23.2 ; sheet U_FPGA_Power/M0
M1: R18.2 ; sheet U_FPGA_Power/M1
M2: R14.2 ; sheet U_FPGA_Power/M2
MOUSECLOCK: U1.A17(IO_L23N_1) ; port MOUSE.CLOCK
MOUSEDATA: U1.B17(IO_L23P_1) ; port MOUSE.DATA
NEXUS_TCK: U1.P21(IO_L38P_3) ; harness JTAG.TCK
NEXUS_TDI: U1.R21(IO_L32P_3) ; harness JTAG.TDI
NEXUS_TDO: U1.B23(IO_L04N_1) ; harness JTAG.TDO
NEXUS_TMS: U1.P19(IO_L35P_3) ; harness JTAG.TMS
ONE_WIRE_DB_PB: U1.AA8(IO_L11P_5) ; port ONE_WIRE_DB_PB
ONE_WIRE_DBID: port ONE_WIRE_DBID, sheet U_1WB_DS2406_EPROM/ONE_WIRE.ID
ONE_WIRE_PIO1: port ONE_WIRE_PIO1, sheet U_1WB_DS2406_EPROM/ONE_WIRE.PIO1
PROG_B: R24.2 ; sheet U_FPGA_Power/PROG_B
REF_CLK: U1.AF14(IO_L32P_4/GCLK0) ; port CLOCKS.REF_CLK
RS232_CTS: U1.A15(IO_L29N_1) ; port RS232.CTS
RS232_RTS: U1.A12(IO_L29P_0) ; port RS232.RTS
RS232_RX: U1.B15(IO_L29P_1) ; port RS232.RXD
RS232_TX: U1.A14(IO) ; port RS232.TXD
SCL: U1.AA7(IO) ; port I2C.SCL
SDA: U1.AA6(IO_L05P_5) ; port I2C.SDA
SPI_CLK: U1.E13(IO) ; port SPI.CLK
SPI_DIN: U1.H12(IO) ; port SPI.DIN
SPI_DOUT: U1.H15(IO_L27P_1) ; port SPI.DOUT
SPI_MODE: U1.E15(IO_L28N_1) ; port SPI.MODE
SPI_SEL: U1.E14(IO_L31P_1) ; port SPI.SEL
SRAM1_A0: U1.AC18(IO_L17P_4)
SRAM1_A1: U1.AC19(IO_L12P_4)
SRAM1_A2: U1.AD21(IO_L08N_4)
SRAM1_A3: U1.AD22(IO_L06N_4/VREF_4)
SRAM1_A4: U1.AD23(IO)
SRAM1_A5: U1.Y16(IO_L24N_4)
SRAM1_A6: U1.Y17(IO/VREF_4)
SRAM1_A7: U1.Y18(IO_L16N_4)
SRAM1_A8: U1.Y19(IO_L11N_4)
SRAM1_A9: U1.Y20(IO_L05P_3)
SRAM1_A10: U1.Y21(IO_L05N_3)
SRAM1_A11: U1.AA20(IO)
SRAM1_A12: U1.AA19(IO_L11P_4)
SRAM1_A13: U1.AA18(IO_L16P_4)
SRAM1_A14: U1.AA17(IO_L19P_4)
SRAM1_A15: U1.AD18(IO_L18N_4)
SRAM1_A16: U1.AD17(IO_L22N_4/VREF_4)
SRAM1_A17: U1.AC17(IO_L19N_4)
SRAM1_A18: U1.AA16(IO_L24P_4)
SRAM1_D0: U1.W15(IO)
SRAM1_D1: U1.AB15(IO_L28P_4)
SRAM1_D2: U1.AB16(IO_L25N_4)
SRAM1_D3: U1.AB17(IO_L22P_4)
SRAM1_D4: U1.AB18(IO_L17N_4)
SRAM1_D5: U1.AB19(IO_L12N_4)
SRAM1_D6: U1.AB20(IO_L09N_4)
SRAM1_D7: U1.AB21(IO_L07N_4)
SRAM1_D8: U1.AA15(IO_L28N_4)
SRAM1_D9: U1.AA14(IO_L30P_4/D3)
SRAM1_D10: U1.W14(IO_L27P_4/D1)
SRAM1_D11: U1.AD25(IO/VREF_4)
SRAM1_D12: U1.AC21(IO_L07P_4)
SRAM1_D13: U1.AC20(IO_L09P_4)
SRAM1_D14: U1.AD19(IO)
SRAM1_D15: U1.AD14(IO_L31P_4/DOUT/BUSY)
SRAM1_NBHE: U1.AD15(IO) ; port SRAM1.NBHE
SRAM1_NBLE: U1.W16(IO) ; port SRAM1.NBLE
SRAM1_NCS: U1.AB14(IO/VREF_4) ; port SRAM1.NCS
SRAM1_NOE: U1.AC16(IO_L25P_4) ; port SRAM1.NOE
SRAM1_NWE: U1.Y14(IO_L30N_4/D2) ; port SRAM1.NWE
SRAM2_A0: U1.T22(IO_L28N_3)
SRAM2_A1: U1.R22(IO_L32N_3)
SRAM2_A2: U1.R19(IO_L31P_3)
SRAM2_A3: U1.P22(IO_L38N_3)
SRAM2_A4: U1.AB23(IO_L02P_3)
SRAM2_A5: U1.T23(IO_L33P_3)
SRAM2_A6: U1.R24(IO_L33N_3)
SRAM2_A7: U1.T19(IO_L27P_3)
SRAM2_A8: U1.P24(IO_L39N_3)
SRAM2_A9: U1.P23(IO_L39P_3)
SRAM2_A10: U1.P26(IO_L40N_3/VREF_3)
SRAM2_A11: U1.P25(IO_L40P_3)
SRAM2_A12: U1.R26(IO_L34N_3)
SRAM2_A13: U1.R25(IO_L34P_3/VREF_3)
SRAM2_A14: U1.T26(IO_L29N_3)
SRAM2_A15: U1.AC26(IO_L03N_3)
SRAM2_A16: U1.AC25(IO_L03P_3)
SRAM2_A17: U1.Y22(IO_L08P_3)
SRAM2_A18: U1.T25(IO_L29P_3)
SRAM2_D0: U1.AA23(IO_L07P_3)
SRAM2_D1: U1.AA24(IO_L07N_3)
SRAM2_D2: U1.Y23(IO_L08N_3)
SRAM2_D3: U1.W23(IO_L17P_3/VREF_3)
SRAM2_D4: U1.W24(IO_L17N_3)
SRAM2_D5: U1.V23(IO_L21N_3)
SRAM2_D6: U1.V24(IO_L22P_3)
SRAM2_D7: U1.U24(IO_L24N_3)
SRAM2_D8: U1.U26(IO_L26N_3)
SRAM2_D9: U1.U25(IO_L26P_3)
SRAM2_D10: U1.V25(IO_L22N_3)
SRAM2_D11: U1.W26(IO_L19N_3)
SRAM2_D12: U1.W25(IO_L19P_3)
SRAM2_D13: U1.Y26(IO_L14N_3)
SRAM2_D14: U1.Y25(IO_L14P_3)
SRAM2_D15: U1.AA26(IO_L09N_3)
SRAM2_NBHE: U1.AB26(IO_L06N_3) ; port SRAM2.NBHE
SRAM2_NBLE: U1.AA25(IO_L09P_3/VREF_3) ; port SRAM2.NBLE
SRAM2_NCS: U1.AB24(IO_L02N_3/VREF_3) ; port SRAM2.NCS
SRAM2_NOE: U1.AB25(IO_L06P_3) ; port SRAM2.NOE
SRAM2_NWE: U1.U23(IO_L24P_3) ; port SRAM2.NWE
STATUS_LED: NT6.1(Net1) ; port STATUS_LED
SW0: U1.AB8(IO_L11N_5/VREF_5)
SW1: U1.AB9(IO)
SW2: U1.AB10(IO_L22P_5)
SW3: U1.AB11(IO_L25N_5)
SW4: U1.AB12(IO_L28N_5/D6)
TCK: R9.2 ; sheet U_FPGA_Power/TCK
TDI: R12.2 ; sheet U_FPGA_Power/TDI
TDO: R10.2 ; sheet U_FPGA_Power/TDO
TMS: R8.2 ; sheet U_FPGA_Power/TMS
UGCLK0: U1.B13(IO_L32N_0/GCLK7)
UGCLK1: U1.AE13(IO_L32N_5/GCLK3)
UGCLK2: U1.AD13(IO_L32P_5/GCLK2)

Not connected (* = marked no-connect by the designer): U1 A3(IO)* A4(IO_L05P_0/VREF_0)* A5(IO)* A6(IO)* A7(IO_L10P_0)* AA3(IO_L07P_6)* AA5(NC)* AA21(IO_L01P_3/VRN_3)* AA22(IO_L01N_3/VRP_3)* AB13(IO_L31P_5/D5)* AB22(IO_L01N_4/VRP_4)* AC22(IO_L01P_4/VRN_4)* AD1(IO_L01P_6/VRN_6)* AD2(IO_L01N_6/VRP_6)* AE7(IO_L10P_5/VRN_5)* AF7(IO_L10N_5/VRP_5)* B3(IO/VREF_0)* B5(IO_L06P_0)* B6(IO_L08P_0)* B7(IO_L10N_0)* B14(IO_L32N_1/GCLK5)* B18(IO_L18N_1)* C25(IO_L01N_2/VRP_2)* C26(IO_L01P_2/VRN_2)* D5(IO_L01P_0/VRN_0)* D14(IO_L31N_1/VREF_1)* D22(IO_L01N_1/VRP_1)* D25(IO_L03N_2/VREF_2)* D26(IO_L03P_2)* E5(IO_L01N_0/VRP_0)* E9(IO_L17N_0)* E16(IO_L25N_1)* E22(IO_L01P_1/VRN_1)* F5(IO_L01N_7/VRP_7)* F6(IO_L01P_7/VRN_7)* F7(IO/VREF_0)* F22(NC)* G6(IO_L05N_7)* G9(IO_L16N_0)* G10(IO/VREF_0)* G11(IO_L24N_0)* G12(IO_L27N_0)* G13(IO_L30N_0)* G14(IO_L30N_1)* G15(IO_L27N_1)* G16(IO_L24N_1)* G25(IO_L10N_2)* H6(IO_L10N_7)* H20(IO_L14N_2)* J6(IO_L16N_7)* K23(IO_L24N_2)* N20(IO_L35P_2)* N22(IO_L38P_2)* N23(IO_L39N_2)* N26(IO_L40P_2/VREF_2)* P20(IO_L35N_3)* R20(IO_L31N_3)* T20(IO_L27N_3)* T21(IO_L28P_3)* U20(IO_L20N_3)* U21(IO_L23P_3/VREF_3)* U22(IO_L23N_3)* V2(IO_L22P_6)* V20(IO_L20P_3)* V21(IO_L16N_3)* V22(IO_L21P_3)* W12(IO_L27P_5)* W20(IO_L10P_3)* W21(IO_L10N_3)* W22(IO_L16P_3)* Y4(IO_L08P_6)*

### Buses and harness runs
bus BUS_A[24..1]
bus BUS_D[31..0]
bus BUS_NBE[3..0]
bus DAU_TFT_BLUE[4..0]
bus DAU_TFT_CL[3..1]
bus DAU_TFT_GREEN[5..0]
bus DAU_TFT_RED[4..0]
bus DIP[7..0]
bus EXTEND_A[49..0]
bus EXTEND_B[49..0]
bus EXTEND_C[49..0]
bus FPGA_ID[3..0]
bus FPGA_M[2..0]
bus IO[35..0]
bus LED[7..0]
bus SRAM1_A[18..0]
bus SRAM1_D[15..0]
bus SRAM2_A[18..0]
bus SRAM2_D[15..0]
bus SW[4..0]
bus UGCLK[2..0]

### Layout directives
net class CLKS: BUS_SDRAM_CLK, BUS_SDRAM_FEEDBACK, FPGA_CLK, FPGA_CLK1, ONE_WIRE_DB_PB, REF_CLK, UGCLK0, UGCLK1, UGCLK2

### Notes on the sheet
- DAUGHTER BOARD I/O
- HOST PERIPHERALS
- JTAG
- PROGRAM
- Host Reset
- (near NT2) FPGA_ID = 0x0
- (near NT2) (Xilinx)
- Status LEDs
- SPI BUS
- DAUGHTER BOARD MEMORY RESOURCES
- CLOCKS
- TFT LCD DISPLAY INTERFACE
- ONE-WIRE CONNECTIONS

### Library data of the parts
NT2-NT6 NT8 = D-002-0002: as NT7 on sheet PSU
R1-R4 = D-100-0088: Resistor, 4K7 1% 0402 (1005); Power Rating: 63 mW; Resistance: 4.7 K
R7-R10 R12 R14 R18 R20 R22-R24 = D-100-0131: Resistor, 100R 1% 0402 (1005); Power Rating: 63 mW
U1 = D-241-0001: FPGA, Xilinx Spartan3-1500 FG676 Speed=4; Supply Voltage: mV

## Sheet FPGA_NonIO.SchDoc: FPGA Power and Programming
size A4; Address1: Level 3, 12a Rodborough Rd; Address2: Frenchs Forest 2086; Address3: NSW; Address4: AUSTRALIA; SheetNumber: 8; SheetTotal: 23
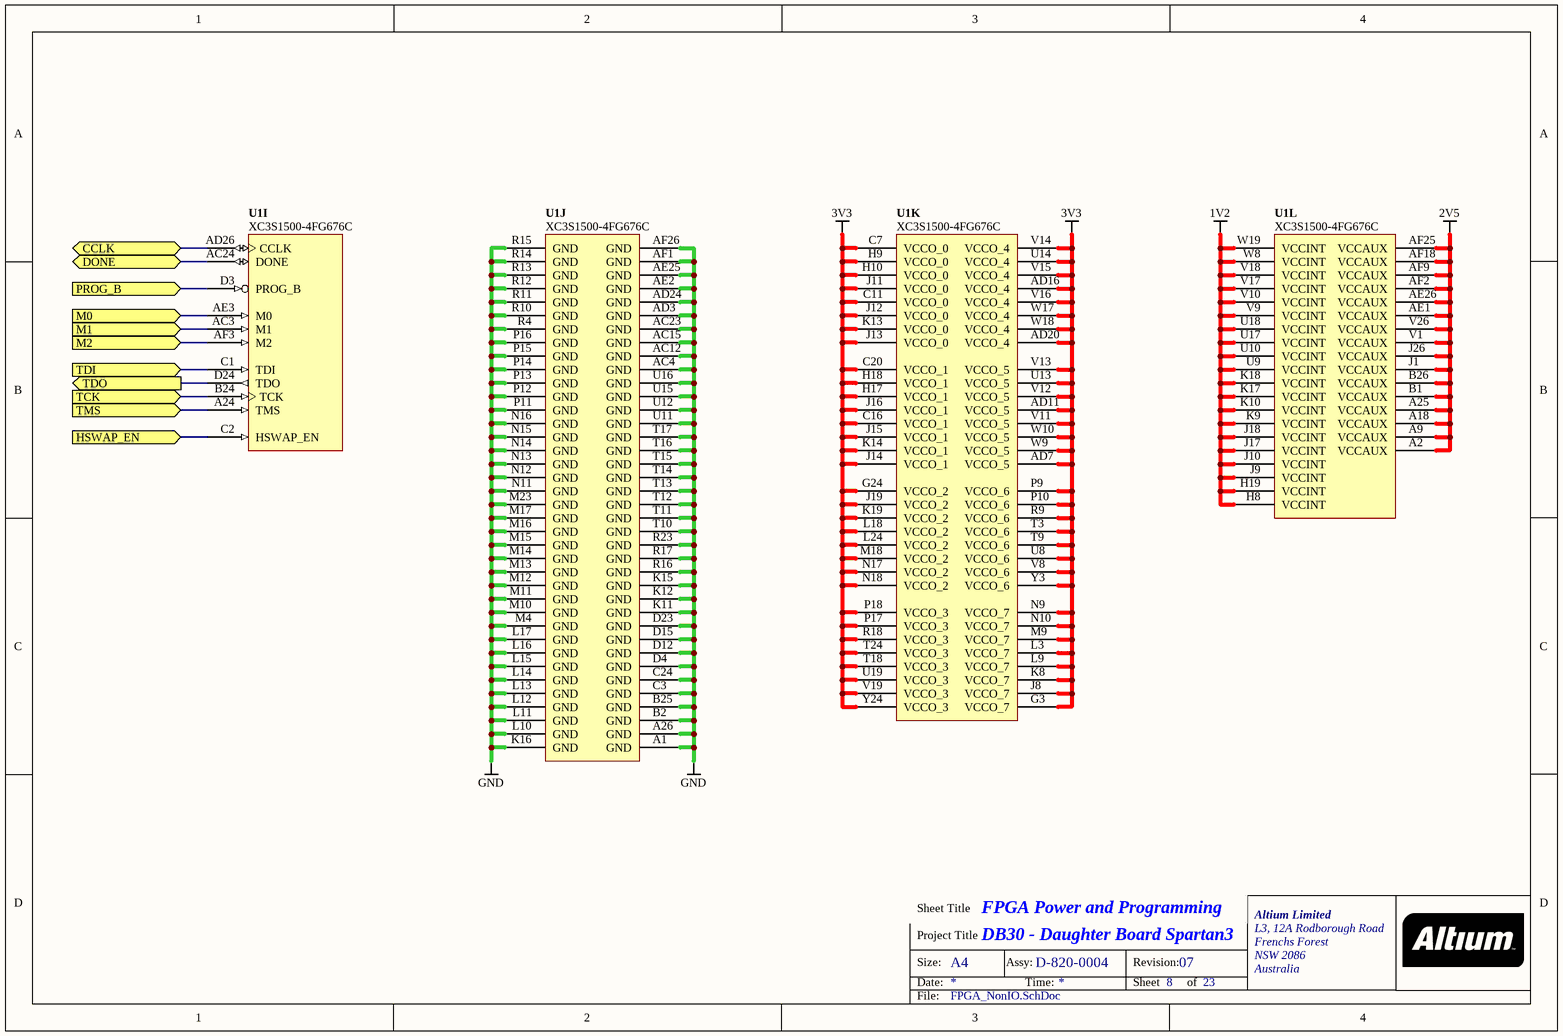
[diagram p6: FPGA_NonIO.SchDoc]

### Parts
U1  XC3S1500-4FG676C  [BGA100P26X26-676]  (parts I,J,K,L of 12)

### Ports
CCLK (bidir), DONE (bidir), HSWAP_EN (in), M0 (in), M1 (in), M2 (in), PROG_B (in), TCK (in), TDI (in), TDO (out), TMS (in)

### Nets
1V2: U1.H8(VCCINT) U1.H19(VCCINT) U1.J9(VCCINT) U1.J10(VCCINT) U1.J17(VCCINT) U1.J18(VCCINT) U1.K9(VCCINT) U1.K10(VCCINT) U1.K17(VCCINT) U1.K18(VCCINT) U1.U9(VCCINT) U1.U10(VCCINT) U1.U17(VCCINT) U1.U18(VCCINT) U1.V9(VCCINT) U1.V10(VCCINT) U1.V17(VCCINT) U1.V18(VCCINT) U1.W8(VCCINT) U1.W19(VCCINT)
2V5: U1.A2(VCCAUX) U1.A9(VCCAUX) U1.A18(VCCAUX) U1.A25(VCCAUX) U1.AE1(VCCAUX) U1.AE26(VCCAUX) U1.AF2(VCCAUX) U1.AF9(VCCAUX) U1.AF18(VCCAUX) U1.AF25(VCCAUX) U1.B1(VCCAUX) U1.B26(VCCAUX) U1.J1(VCCAUX) U1.J26(VCCAUX) U1.V1(VCCAUX) U1.V26(VCCAUX)
3V3: U1.AD7(VCCO_5) U1.AD11(VCCO_5) U1.AD16(VCCO_4) U1.AD20(VCCO_4) U1.C7(VCCO_0) U1.C11(VCCO_0) U1.C16(VCCO_1) U1.C20(VCCO_1) U1.G3(VCCO_7) U1.G24(VCCO_2) U1.H9(VCCO_0) U1.H10(VCCO_0) U1.H17(VCCO_1) U1.H18(VCCO_1) U1.J8(VCCO_7) U1.J11(VCCO_0) U1.J12(VCCO_0) U1.J13(VCCO_0) U1.J14(VCCO_1) U1.J15(VCCO_1) U1.J16(VCCO_1) U1.J19(VCCO_2) U1.K8(VCCO_7) U1.K13(VCCO_0) U1.K14(VCCO_1) U1.K19(VCCO_2) U1.L3(VCCO_7) U1.L9(VCCO_7) U1.L18(VCCO_2) U1.L24(VCCO_2) U1.M9(VCCO_7) U1.M18(VCCO_2) U1.N9(VCCO_7) U1.N10(VCCO_7) U1.N17(VCCO_2) U1.N18(VCCO_2) U1.P9(VCCO_6) U1.P10(VCCO_6) U1.P17(VCCO_3) U1.P18(VCCO_3) U1.R9(VCCO_6) U1.R18(VCCO_3) U1.T3(VCCO_6) U1.T9(VCCO_6) U1.T18(VCCO_3) U1.T24(VCCO_3) U1.U8(VCCO_6) U1.U13(VCCO_5) U1.U14(VCCO_4) U1.U19(VCCO_3) U1.V8(VCCO_6) U1.V11(VCCO_5) U1.V12(VCCO_5) U1.V13(VCCO_5) U1.V14(VCCO_4) U1.V15(VCCO_4) U1.V16(VCCO_4) U1.V19(VCCO_3) U1.W9(VCCO_5) U1.W10(VCCO_5) U1.W17(VCCO_4) U1.W18(VCCO_4) U1.Y3(VCCO_6) U1.Y24(VCCO_3)
GND: U1.A1(GND) U1.A26(GND) U1.AC4(GND) U1.AC12(GND) U1.AC15(GND) U1.AC23(GND) U1.AD3(GND) U1.AD24(GND) U1.AE2(GND) U1.AE25(GND) U1.AF1(GND) U1.AF26(GND) U1.B2(GND) U1.B25(GND) U1.C3(GND) U1.C24(GND) U1.D4(GND) U1.D12(GND) U1.D15(GND) U1.D23(GND) U1.K11(GND) U1.K12(GND) U1.K15(GND) U1.K16(GND) U1.L10(GND) U1.L11(GND) U1.L12(GND) U1.L13(GND) U1.L14(GND) U1.L15(GND) U1.L16(GND) U1.L17(GND) U1.M4(GND) U1.M10(GND) U1.M11(GND) U1.M12(GND) U1.M13(GND) U1.M14(GND) U1.M15(GND) U1.M16(GND) U1.M17(GND) U1.M23(GND) U1.N11(GND) U1.N12(GND) U1.N13(GND) U1.N14(GND) U1.N15(GND) U1.N16(GND) U1.P11(GND) U1.P12(GND) U1.P13(GND) U1.P14(GND) U1.P15(GND) U1.P16(GND) U1.R4(GND) U1.R10(GND) U1.R11(GND) U1.R12(GND) U1.R13(GND) U1.R14(GND) U1.R15(GND) U1.R16(GND) U1.R17(GND) U1.R23(GND) U1.T10(GND) U1.T11(GND) U1.T12(GND) U1.T13(GND) U1.T14(GND) U1.T15(GND) U1.T16(GND) U1.T17(GND) U1.U11(GND) U1.U12(GND) U1.U15(GND) U1.U16(GND)
CCLK: U1.AD26(CCLK) ; port CCLK
DONE: U1.AC24(DONE) ; port DONE
HSWAP_EN: U1.C2(HSWAP_EN) ; port HSWAP_EN
M0: U1.AE3(M0) ; port M0
M1: U1.AC3(M1) ; port M1
M2: U1.AF3(M2) ; port M2
PROG_B: U1.D3(PROG_B) ; port PROG_B
TCK: U1.B24(TCK) ; port TCK
TDI: U1.C1(TDI) ; port TDI
TDO: U1.D24(TDO) ; port TDO
TMS: U1.A24(TMS) ; port TMS

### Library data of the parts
U1 = D-241-0001: as U1 on sheet FPGA

## Sheet Bypass_FPGA_3V3.SchDoc: FPGA Bypass 3V3
size A4; Organization: Altium Limited.; Address1: Level 3, 12a Rodborough Rd; Address2: Frenchs Forest 2086; Address3: NSW; Address4: AUSTRALIA; SheetNumber: 7; SheetTotal: 23; PageSetup: Record=PageOptions|CenterHorizontal=True|CenterVertical=True|PrintScale=0.97|XCorrection=1.00|YCorrection=1.00|PrintKind=0|BorderSize=5000000|LeftOffset=0|BottomOffset=0|Orientation=2|PaperLength=1000|PaperWidth=1000|Scale=100|PaperSource=7|PrintQuality=-4|MediaType=1|DitherType=10|PaperKind=A4 (210 x 297 mm)|PrintScaleMode=1
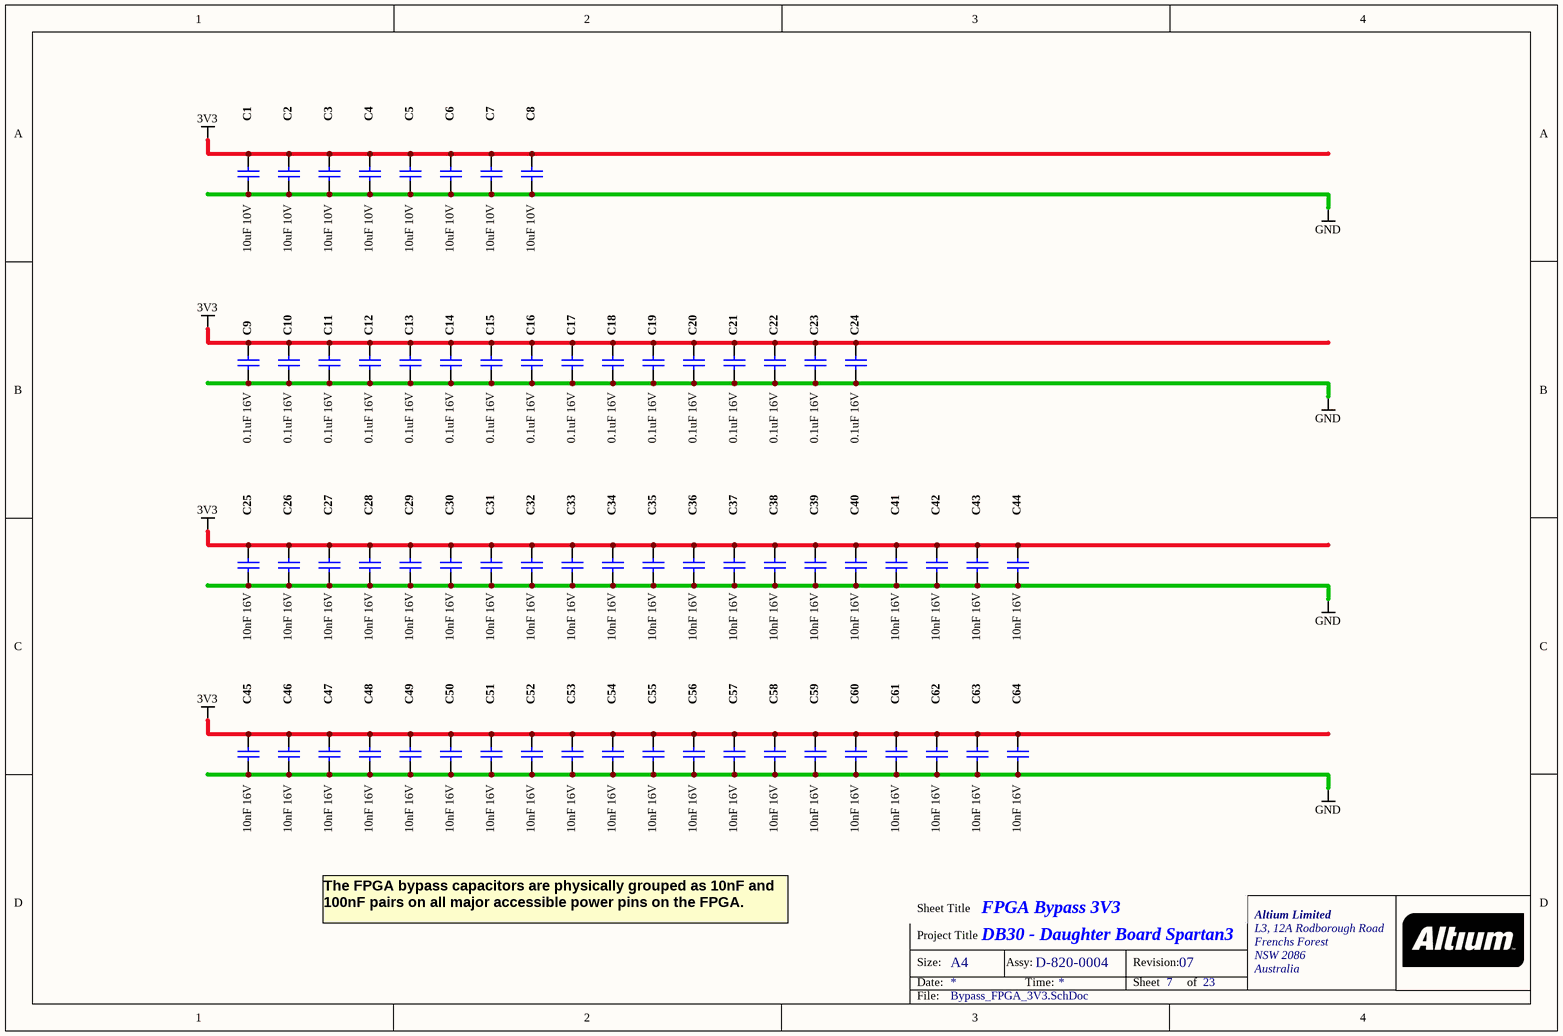
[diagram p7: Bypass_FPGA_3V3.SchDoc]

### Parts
(Parts that share a designator on the sheet are numbered #1, #2 ... from top to bottom, then left to right.)
C1#1  10uF 10V  [CAPC2012-STAR]
C2#1  10uF 10V  [CAPC2012-STAR]
C3#1  10uF 10V  [CAPC2012-STAR]
C4#1  10uF 10V  [CAPC2012-STAR]
C5#1  10uF 10V  [CAPC2012-STAR]
C6#1  10uF 10V  [CAPC2012-STAR]
C7#1  10uF 10V  [CAPC2012-STAR]
C8#1  10uF 10V  [CAPC2012-STAR]
C9#1  0.1uF 16V  [CAPC1005-STAR]
C10#1  0.1uF 16V  [CAPC1005-STAR]
C11#1  0.1uF 16V  [CAPC1005-STAR]
C12#1  0.1uF 16V  [CAPC1005-STAR]
C13#1  0.1uF 16V  [CAPC1005-STAR]
C14#1  0.1uF 16V  [CAPC1005-STAR]
C15#1  0.1uF 16V  [CAPC1005-STAR]
C16#1  0.1uF 16V  [CAPC1005-STAR]
C17#1  0.1uF 16V  [CAPC1005-STAR]
C18#1  0.1uF 16V  [CAPC1005-STAR]
C19#1  0.1uF 16V  [CAPC1005-STAR]
C20#1  0.1uF 16V  [CAPC1005-STAR]
C21  0.1uF 16V  [CAPC1005-STAR]
C22  0.1uF 16V  [CAPC1005-STAR]
C23  0.1uF 16V  [CAPC1005-STAR]
C24  0.1uF 16V  [CAPC1005-STAR]
C25  10nF 16V  [CAPC1005-STAR]
C26  10nF 16V  [CAPC1005-STAR]
C27  10nF 16V  [CAPC1005-STAR]
C28  10nF 16V  [CAPC1005-STAR]
C29  10nF 16V  [CAPC1005-STAR]
C30  10nF 16V  [CAPC1005-STAR]
C31  10nF 16V  [CAPC1005-STAR]
C32  10nF 16V  [CAPC1005-STAR]
C33  10nF 16V  [CAPC1005-STAR]
C34  10nF 16V  [CAPC1005-STAR]
C35  10nF 16V  [CAPC1005-STAR]
C36  10nF 16V  [CAPC1005-STAR]
C37  10nF 16V  [CAPC1005-STAR]
C38  10nF 16V  [CAPC1005-STAR]
C39  10nF 16V  [CAPC1005-STAR]
C40  10nF 16V  [CAPC1005-STAR]
C41  10nF 16V  [CAPC1005-STAR]
C42  10nF 16V  [CAPC1005-STAR]
C43  10nF 16V  [CAPC1005-STAR]
C44  10nF 16V  [CAPC1005-STAR]
C45  10nF 16V  [CAPC1005-STAR]
C46  10nF 16V  [CAPC1005-STAR]
C47  10nF 16V  [CAPC1005-STAR]
C48  10nF 16V  [CAPC1005-STAR]
C49  10nF 16V  [CAPC1005-STAR]
C50  10nF 16V  [CAPC1005-STAR]
C51  10nF 16V  [CAPC1005-STAR]
C52  10nF 16V  [CAPC1005-STAR]
C53  10nF 16V  [CAPC1005-STAR]
C54  10nF 16V  [CAPC1005-STAR]
C55  10nF 16V  [CAPC1005-STAR]
C56  10nF 16V  [CAPC1005-STAR]
C57  10nF 16V  [CAPC1005-STAR]
C58  10nF 16V  [CAPC1005-STAR]
C59  10nF 16V  [CAPC1005-STAR]
C60  10nF 16V  [CAPC1005-STAR]
C61  10nF 16V  [CAPC1005-STAR]
C62  10nF 16V  [CAPC1005-STAR]
C63  10nF 16V  [CAPC1005-STAR]
C64  10nF 16V  [CAPC1005-STAR]

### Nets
3V3: C1#1.1 C2#1.1 C3#1.1 C4#1.1 C5#1.1 C6#1.1 C7#1.1 C8#1.1 C9#1.1 C10#1.1 C11#1.1 C12#1.1 C13#1.1 C14#1.1 C15#1.1 C16#1.1 C17#1.1 C18#1.1 C19#1.1 C20#1.1 C21.1 C22.1 C23.1 C24.1 C25.1 C26.1 C27.1 C28.1 C29.1 C30.1 C31.1 C32.1 C33.1 C34.1 C35.1 C36.1 C37.1 C38.1 C39.1 C40.1 C41.1 C42.1 C43.1 C44.1 C45.1 C46.1 C47.1 C48.1 C49.1 C50.1 C51.1 C52.1 C53.1 C54.1 C55.1 C56.1 C57.1 C58.1 C59.1 C60.1 C61.1 C62.1 C63.1 C64.1
GND: C1#1.2 C2#1.2 C3#1.2 C4#1.2 C5#1.2 C6#1.2 C7#1.2 C8#1.2 C9#1.2 C10#1.2 C11#1.2 C12#1.2 C13#1.2 C14#1.2 C15#1.2 C16#1.2 C17#1.2 C18#1.2 C19#1.2 C20#1.2 C21.2 C22.2 C23.2 C24.2 C25.2 C26.2 C27.2 C28.2 C29.2 C30.2 C31.2 C32.2 C33.2 C34.2 C35.2 C36.2 C37.2 C38.2 C39.2 C40.2 C41.2 C42.2 C43.2 C44.2 C45.2 C46.2 C47.2 C48.2 C49.2 C50.2 C51.2 C52.2 C53.2 C54.2 C55.2 C56.2 C57.2 C58.2 C59.2 C60.2 C61.2 C62.2 C63.2 C64.2

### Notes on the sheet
- The FPGA bypass capacitors are physically grouped as 10nF and 100nF pairs on all major accessible power pins on the FPGA.

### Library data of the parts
C1#1 C2#1 C3#1 C4#1 C5#1 C6#1 C7#1 C8#1 = D-101-0087: as C23_CM on sheet PSU
C9#1 C10#1 C11#1 C12#1 C13#1 C14#1 C15#1 C16#1 C17#1 C18#1 C19#1 C20#1 C21-C24 = D-101-0080: Capacitor, Ceramic, 0.1uF 10% 16V 0402 (1005) X7R; Polarity: Non-Polarized
C25-C64 = D-101-0077: Capacitor, Ceramic, 10nF 10% 16V 0402 (1005) X7R; Polarity: Non-Polarized

## Sheet Bypass_FPGA_2V5.SchDoc: FPGA Bypass 2V5
size A4; Organization: Altium Limited.; Address1: Level 3, 12a Rodborough Rd; Address2: Frenchs Forest 2086; Address3: NSW; Address4: AUSTRALIA; SheetNumber: 6; SheetTotal: 23; PageSetup: Record=PageOptions|CenterHorizontal=True|CenterVertical=True|PrintScale=0.97|XCorrection=1.00|YCorrection=1.00|PrintKind=0|BorderSize=5000000|LeftOffset=0|BottomOffset=0|Orientation=2|PaperLength=1000|PaperWidth=1000|Scale=100|PaperSource=7|PrintQuality=-4|MediaType=1|DitherType=10|PaperKind=A4 (210 x 297 mm)|PrintScaleMode=1
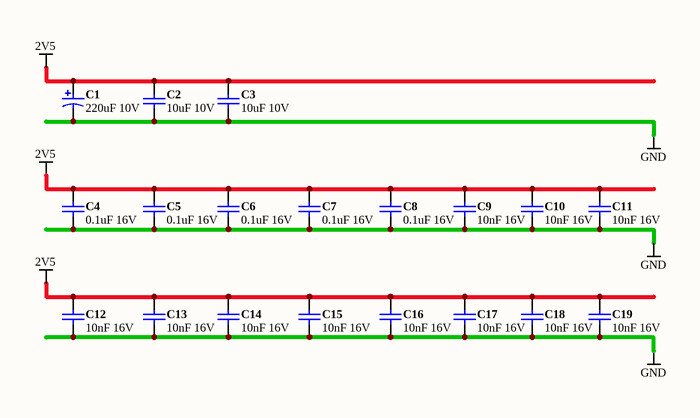
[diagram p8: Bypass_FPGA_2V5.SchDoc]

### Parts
(Parts that share a designator on the sheet are numbered #1, #2 ... from top to bottom, then left to right.)
C1#2  220uF 10V  [CAPC7343-STAR]
C2#2  10uF 10V  [CAPC2012-STAR]
C3#2  10uF 10V  [CAPC2012-STAR]
C4#2  0.1uF 16V  [CAPC1005-STAR]
C5#2  0.1uF 16V  [CAPC1005-STAR]
C6#2  0.1uF 16V  [CAPC1005-STAR]
C7#2  0.1uF 16V  [CAPC1005-STAR]
C8#2  0.1uF 16V  [CAPC1005-STAR]
C9#2  10nF 16V  [CAPC1005-STAR]
C10#2  10nF 16V  [CAPC1005-STAR]
C11#2  10nF 16V  [CAPC1005-STAR]
C12#2  10nF 16V  [CAPC1005-STAR]
C13#2  10nF 16V  [CAPC1005-STAR]
C14#2  10nF 16V  [CAPC1005-STAR]
C15#2  10nF 16V  [CAPC1005-STAR]
C16#2  10nF 16V  [CAPC1005-STAR]
C17#2  10nF 16V  [CAPC1005-STAR]
C18#2  10nF 16V  [CAPC1005-STAR]
C19#2  10nF 16V  [CAPC1005-STAR]

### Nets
2V5: C1#2.1 C2#2.1 C3#2.1 C4#2.1 C5#2.1 C6#2.1 C7#2.1 C8#2.1 C9#2.1 C10#2.1 C11#2.1 C12#2.1 C13#2.1 C14#2.1 C15#2.1 C16#2.1 C17#2.1 C18#2.1 C19#2.1
GND: C1#2.2 C2#2.2 C3#2.2 C4#2.2 C5#2.2 C6#2.2 C7#2.2 C8#2.2 C9#2.2 C10#2.2 C11#2.2 C12#2.2 C13#2.2 C14#2.2 C15#2.2 C16#2.2 C17#2.2 C18#2.2 C19#2.2

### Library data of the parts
C1#2 = D-101-0088: Capacitor, Tantalum, 220uF 10% 10V MCCT-D (7343-31); Polarity: Polarized
C2#2 C3#2 = D-101-0087: as C23_CM on sheet PSU
C4#2 C5#2 C6#2 C7#2 C8#2 = D-101-0080: as C9#1 on sheet Bypass_FPGA_3V3
C9#2 C10#2 C11#2 C12#2 C13#2 C14#2 C15#2 C16#2 C17#2 C18#2 C19#2 = D-101-0077: as C25 on sheet Bypass_FPGA_3V3

## Sheet Bypass_FPGA_1V2.SchDoc: FPGA Bypass 1V2
size A4; Organization: Altium Limited.; Address1: Level 3, 12a Rodborough Rd; Address2: Frenchs Forest 2086; Address3: NSW; Address4: AUSTRALIA; SheetNumber: 5; SheetTotal: 23; PageSetup: Record=PageOptions|CenterHorizontal=True|CenterVertical=True|PrintScale=0.97|XCorrection=1.00|YCorrection=1.00|PrintKind=0|BorderSize=5000000|LeftOffset=0|BottomOffset=0|Orientation=2|PaperLength=1000|PaperWidth=1000|Scale=100|PaperSource=7|PrintQuality=-4|MediaType=1|DitherType=10|PaperKind=A4 (210 x 297 mm)|PrintScaleMode=1
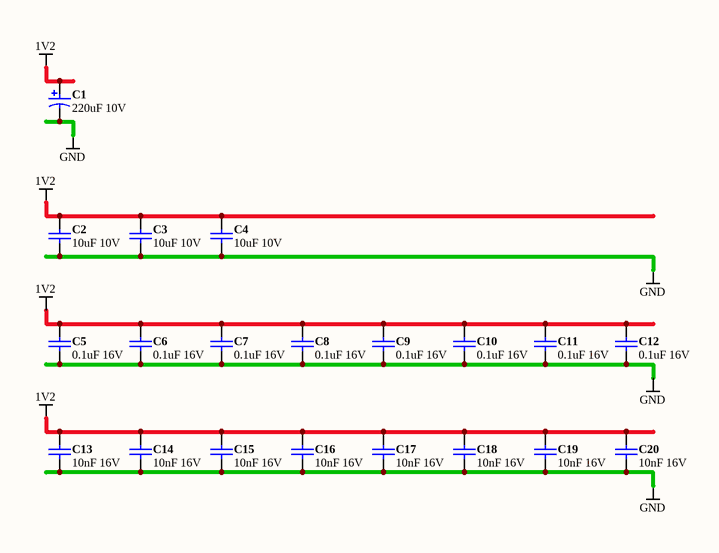
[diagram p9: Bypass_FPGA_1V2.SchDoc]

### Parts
(Parts that share a designator on the sheet are numbered #1, #2 ... from top to bottom, then left to right.)
C1#3  220uF 10V  [CAPC7343-STAR]
C2#3  10uF 10V  [CAPC2012-STAR]
C3#3  10uF 10V  [CAPC2012-STAR]
C4#3  10uF 10V  [CAPC2012-STAR]
C5#3  0.1uF 16V  [CAPC1005-STAR]
C6#3  0.1uF 16V  [CAPC1005-STAR]
C7#3  0.1uF 16V  [CAPC1005-STAR]
C8#3  0.1uF 16V  [CAPC1005-STAR]
C9#3  0.1uF 16V  [CAPC1005-STAR]
C10#3  0.1uF 16V  [CAPC1005-STAR]
C11#3  0.1uF 16V  [CAPC1005-STAR]
C12#3  0.1uF 16V  [CAPC1005-STAR]
C13#3  10nF 16V  [CAPC1005-STAR]
C14#3  10nF 16V  [CAPC1005-STAR]
C15#3  10nF 16V  [CAPC1005-STAR]
C16#3  10nF 16V  [CAPC1005-STAR]
C17#3  10nF 16V  [CAPC1005-STAR]
C18#3  10nF 16V  [CAPC1005-STAR]
C19#3  10nF 16V  [CAPC1005-STAR]
C20#2  10nF 16V  [CAPC1005-STAR]

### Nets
1V2: C1#3.1 C2#3.1 C3#3.1 C4#3.1 C5#3.1 C6#3.1 C7#3.1 C8#3.1 C9#3.1 C10#3.1 C11#3.1 C12#3.1 C13#3.1 C14#3.1 C15#3.1 C16#3.1 C17#3.1 C18#3.1 C19#3.1 C20#2.1
GND: C1#3.2 C2#3.2 C3#3.2 C4#3.2 C5#3.2 C6#3.2 C7#3.2 C8#3.2 C9#3.2 C10#3.2 C11#3.2 C12#3.2 C13#3.2 C14#3.2 C15#3.2 C16#3.2 C17#3.2 C18#3.2 C19#3.2 C20#2.2

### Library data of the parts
C1#3 = D-101-0088: as C1#2 on sheet Bypass_FPGA_2V5
C2#3 C3#3 C4#3 = D-101-0087: as C23_CM on sheet PSU
C5#3 C6#3 C7#3 C8#3 C9#3 C10#3 C11#3 C12#3 = D-101-0080: as C9#1 on sheet Bypass_FPGA_3V3
C13#3 C14#3 C15#3 C16#3 C17#3 C18#3 C19#3 C20#2 = D-101-0077: as C25 on sheet Bypass_FPGA_3V3

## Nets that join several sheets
1V2: PSU (TP4.1), FPGA_NonIO (20 pins), Bypass_FPGA_1V2 (20 pins)
2V5: PSU (R1T.2 TP2.1), FPGA_NonIO (16 pins), Bypass_FPGA_2V5 (19 pins)
3V3: PSU (C23_CM.1 C24_CM.1 TP1.1), FPGA (R1.2 R2.2 R3.2 R4.2), FPGA_NonIO (64 pins), Bypass_FPGA_3V3 (64 pins)
GND: PSU (C23_CM.2 C24_CM.2 NT7.2 TP0.1), FPGA (NT2.2 NT3.2 NT4.2 NT5.2), FPGA_NonIO (76 pins), Bypass_FPGA_3V3 (64 pins), Bypass_FPGA_2V5 (19 pins), Bypass_FPGA_1V2 (20 pins)
CCLK: FPGA (R20.2), FPGA_NonIO (U1.AD26)
DONE: FPGA (R22.2), FPGA_NonIO (U1.AC24)
HSWAP_EN: FPGA (R7.2), FPGA_NonIO (U1.C2)
M0: FPGA (R23.2), FPGA_NonIO (U1.AE3)
M1: FPGA (R18.2), FPGA_NonIO (U1.AC3)
M2: FPGA (R14.2), FPGA_NonIO (U1.AF3)
PROG_B: FPGA (R24.2), FPGA_NonIO (U1.D3)
TCK: FPGA (R9.2), FPGA_NonIO (U1.B24)
TDI: FPGA (R12.2), FPGA_NonIO (U1.C1)
TDO: FPGA (R10.2), FPGA_NonIO (U1.D24)
TMS: FPGA (R8.2), FPGA_NonIO (U1.A24)

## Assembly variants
Production: not fitted RN1 RN2 RN3 RN4 RN5 RN6 RN7 RN8 RN17 RN18 RN19 RN20 RN21 RN22 RN23 RN24 RN25 RN26 RN27 RN28 RN29 RN30 RN31 RN32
